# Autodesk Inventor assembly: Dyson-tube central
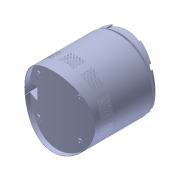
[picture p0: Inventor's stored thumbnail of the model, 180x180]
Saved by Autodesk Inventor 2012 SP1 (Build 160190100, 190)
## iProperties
Created: 2012-11
Part Number: Dyson-tube central
Document SubType Name: Assembly
Designer: Administrateur
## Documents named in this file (5)
- D:\Cours\1-Cours-2013-14\Dropbox\1SI\1. Besoin\Dyson\Composants importés\Dyson Air Multiplier-Assemblage final\Dyson-tube central.iam
- D:\Cours\1-Cours-2013-14\Dropbox\1SI\1. Besoin\Dyson\Composants importés\Dyson Air Multiplier-Assemblage final\Dyson-Partie centre cylindre filtration.ipt
- D:\Cours\1-Cours-2013-14\Dropbox\1SI\1. Besoin\Dyson\Composants importés\Dyson Air Multiplier-Assemblage final\Dyson-Partie centre joint noir.ipt
- D:\Cours\1-Cours-2013-14\Dropbox\1SI\1. Besoin\Dyson\Composants importés\Dyson Air Multiplier-Assemblage final\Dyson-partie centre motorisation.iam
- D:\Cours\1-Cours-2013-14\Dropbox\1SI\1. Besoin\Dyson\Composants importés\Dyson Air Multiplier-Assemblage final\Dyson-Partie inf. cercle ABS noir.ipt
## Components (4 placed, 4 different names)
1. Dyson-Partie centre cylindre filtration:1 — Placage:1, Placage:2, Placage:3, Placage:4, Placage:5
2. Dyson-Partie centre joint noir:1 — Placage:4, Placage:5
3. Dyson-partie centre motorisation:1 [sub-assembly]
4. Dyson-Partie inf. cercle ABS noir:1 — Placage:1, Placage:2, Placage:3
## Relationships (5: Mate 5)
- Placage:1 [Mate]: Dyson-Partie centre cylindre filtration:1 ↔ Dyson-Partie inf. cercle ABS noir:1
- Placage:2 [Mate]: Dyson-Partie centre cylindre filtration:1 ↔ Dyson-Partie inf. cercle ABS noir:1
- Placage:3 [Mate]: Dyson-Partie centre cylindre filtration:1 ↔ Dyson-Partie inf. cercle ABS noir:1
- Placage:4 [Mate]: Dyson-Partie centre cylindre filtration:1 ↔ Dyson-Partie centre joint noir:1
- Placage:5 [Mate]: Dyson-Partie centre cylindre filtration:1 ↔ Dyson-Partie centre joint noir:1
